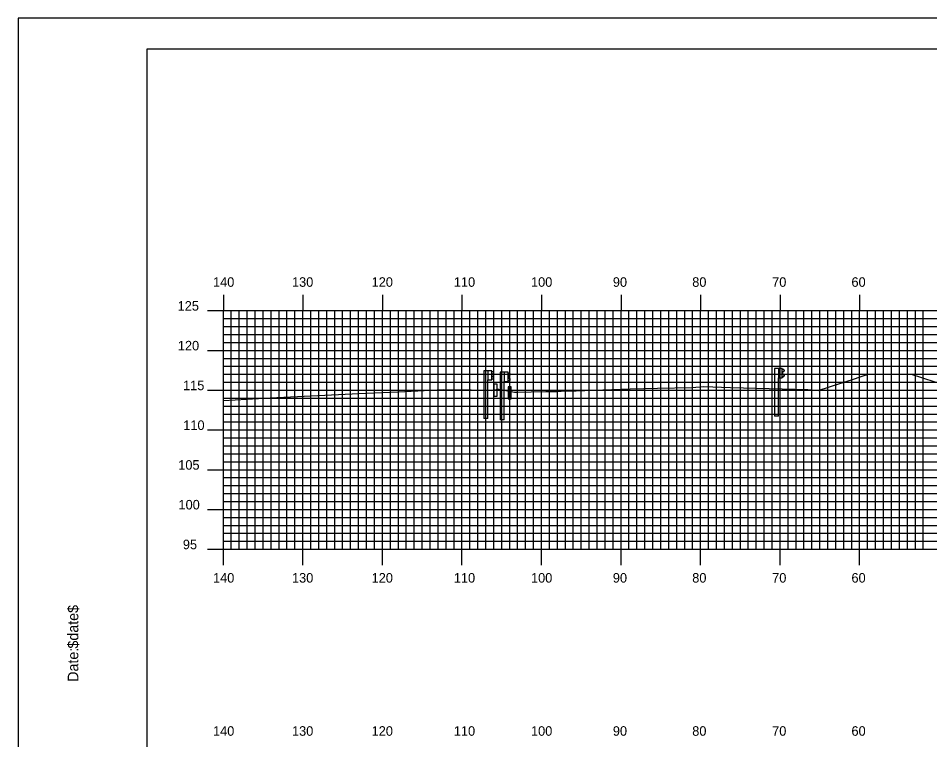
# Model space of a CAD drawing. Extents: x 1754708 to 1755051, y 442591 to 442811.
# Drawn here: x 1754707.7 to 1754822.3, y 442719.8 to 442810.5 of the extents above; entities that cross this region are included whole.
import ezdxf

# ---------------------------------------------------------------- set-up
doc = ezdxf.new("R2010")
doc.units = 0
for name, color, linetype in [('BORDER', 7, 'Continuous'), ('H_V ANNOTATION', 7, 'Continuous'), ('M_Roadway_Centerline', 7, 'Continuous'), ('MAJOR', 7, 'Continuous'), ('MINOR', 7, 'Continuous'), ('PLOT BOUNDARY', 7, 'Continuous'), ('S_Curb_Type_1', 7, 'Continuous'), ('S_Guardrail_Beam', 7, 'Continuous'), ('S_Roadway_Centerline', 7, 'Continuous')]:
    doc.layers.add(name, color=color, linetype=linetype)

msp = doc.modelspace()

# ---------------------------------------------------------------- linework, layer by layer
at = {"layer": 'BORDER'}
msp.add_lwpolyline([(1754723.92, 442596.67), (1755043.92, 442596.67), (1755043.92, 442806.67), (1754723.92, 442806.67)], close=True, dxfattribs=at)
at = {"layer": 'MAJOR'}
for p, q in [((1754733.52, 442775.77), (1754733.52, 442773.77)), ((1754743.52, 442775.77), (1754743.52, 442773.77)), ((1754753.52, 442775.77), (1754753.52, 442773.77)), ((1754763.52, 442775.77), (1754763.52, 442773.77)), ((1754773.52, 442775.77), (1754773.52, 442773.77)), ((1754783.52, 442775.77), (1754783.52, 442773.77)), ((1754793.52, 442775.77), (1754793.52, 442773.77)), ((1754803.52, 442775.77), (1754803.52, 442773.77)), ((1754813.52, 442775.77), (1754813.52, 442773.77)), ((1754731.51, 442773.77), (1754733.52, 442773.77)), ((1754733.52, 442773.77), (1755013.52, 442773.77)), ((1754733.52, 442743.77), (1754733.52, 442773.77)), ((1754733.52, 442743.77), (1754733.52, 442773.77)), ((1754733.52, 442773.77), (1755013.52, 442773.77)), ((1754743.52, 442743.77), (1754743.52, 442773.77)), ((1754753.52, 442743.77), (1754753.52, 442773.77)), ((1754763.52, 442743.77), (1754763.52, 442773.77)), ((1754773.52, 442743.77), (1754773.52, 442773.77)), ((1754783.52, 442743.77), (1754783.52, 442773.77)), ((1754793.52, 442743.77), (1754793.52, 442773.77)), ((1754803.52, 442743.77), (1754803.52, 442773.77)), ((1754813.52, 442743.77), (1754813.52, 442773.77)), ((1754731.51, 442768.77), (1754733.52, 442768.77)), ((1754733.52, 442768.77), (1755013.52, 442768.77)), ((1754731.51, 442763.77), (1754733.52, 442763.77)), ((1754733.52, 442763.77), (1755013.52, 442763.77)), ((1754731.51, 442758.77), (1754733.52, 442758.77)), ((1754733.52, 442758.77), (1755013.52, 442758.77)), ((1754731.51, 442753.77), (1754733.52, 442753.77)), ((1754733.52, 442753.77), (1755013.52, 442753.77)), ((1754731.51, 442748.77), (1754733.52, 442748.77)), ((1754733.52, 442748.77), (1755013.52, 442748.77)), ((1754731.51, 442743.77), (1754733.52, 442743.77)), ((1754733.52, 442743.77), (1755013.52, 442743.77)), ((1754733.52, 442743.77), (1755013.52, 442743.77)), ((1754733.52, 442741.77), (1754733.52, 442743.77)), ((1754743.52, 442741.77), (1754743.52, 442743.77)), ((1754753.52, 442741.77), (1754753.52, 442743.77)), ((1754763.52, 442741.77), (1754763.52, 442743.77)), ((1754773.52, 442741.77), (1754773.52, 442743.77)), ((1754783.52, 442741.77), (1754783.52, 442743.77)), ((1754793.52, 442741.77), (1754793.52, 442743.77)), ((1754803.52, 442741.77), (1754803.52, 442743.77)), ((1754813.52, 442741.77), (1754813.52, 442743.77))]:
    msp.add_line(p, q, dxfattribs=at)
at = {"layer": 'MINOR'}
for p, q in [((1754734.52, 442743.77), (1754734.52, 442773.77)), ((1754735.52, 442743.77), (1754735.52, 442773.77)), ((1754736.52, 442743.77), (1754736.52, 442773.77)), ((1754737.52, 442743.77), (1754737.52, 442773.77)), ((1754738.52, 442743.77), (1754738.52, 442773.77)), ((1754739.52, 442743.77), (1754739.52, 442773.77)), ((1754740.52, 442743.77), (1754740.52, 442773.77)), ((1754741.52, 442743.77), (1754741.52, 442773.77)), ((1754742.52, 442743.77), (1754742.52, 442773.77)), ((1754744.52, 442743.77), (1754744.52, 442773.77)), ((1754745.52, 442743.77), (1754745.52, 442773.77)), ((1754746.52, 442743.77), (1754746.52, 442773.77)), ((1754747.52, 442743.77), (1754747.52, 442773.77)), ((1754748.52, 442743.77), (1754748.52, 442773.77)), ((1754749.52, 442743.77), (1754749.52, 442773.77)), ((1754750.52, 442743.77), (1754750.52, 442773.77)), ((1754751.52, 442743.77), (1754751.52, 442773.77)), ((1754752.52, 442743.77), (1754752.52, 442773.77)), ((1754754.52, 442743.77), (1754754.52, 442773.77)), ((1754755.52, 442743.77), (1754755.52, 442773.77)), ((1754756.52, 442743.77), (1754756.52, 442773.77)), ((1754757.52, 442743.77), (1754757.52, 442773.77)), ((1754758.52, 442743.77), (1754758.52, 442773.77)), ((1754759.52, 442743.77), (1754759.52, 442773.77)), ((1754760.52, 442743.77), (1754760.52, 442773.77)), ((1754761.52, 442743.77), (1754761.52, 442773.77)), ((1754762.52, 442743.77), (1754762.52, 442773.77)), ((1754764.52, 442743.77), (1754764.52, 442773.77)), ((1754765.52, 442743.77), (1754765.52, 442773.77)), ((1754766.52, 442743.77), (1754766.52, 442773.77)), ((1754767.52, 442743.77), (1754767.52, 442773.77)), ((1754768.52, 442743.77), (1754768.52, 442773.77)), ((1754769.52, 442743.77), (1754769.52, 442773.77)), ((1754770.52, 442743.77), (1754770.52, 442773.77)), ((1754771.52, 442743.77), (1754771.52, 442773.77)), ((1754772.52, 442743.77), (1754772.52, 442773.77)), ((1754774.52, 442743.77), (1754774.52, 442773.77)), ((1754775.52, 442743.77), (1754775.52, 442773.77)), ((1754776.52, 442743.77), (1754776.52, 442773.77)), ((1754777.52, 442743.77), (1754777.52, 442773.77)), ((1754778.52, 442743.77), (1754778.52, 442773.77)), ((1754779.52, 442743.77), (1754779.52, 442773.77)), ((1754780.52, 442743.77), (1754780.52, 442773.77)), ((1754781.52, 442743.77), (1754781.52, 442773.77)), ((1754782.52, 442743.77), (1754782.52, 442773.77)), ((1754784.52, 442743.77), (1754784.52, 442773.77)), ((1754785.52, 442743.77), (1754785.52, 442773.77)), ((1754786.52, 442743.77), (1754786.52, 442773.77)), ((1754787.52, 442743.77), (1754787.52, 442773.77)), ((1754788.52, 442743.77), (1754788.52, 442773.77)), ((1754789.52, 442743.77), (1754789.52, 442773.77)), ((1754790.52, 442743.77), (1754790.52, 442773.77)), ((1754791.52, 442743.77), (1754791.52, 442773.77)), ((1754792.52, 442743.77), (1754792.52, 442773.77)), ((1754794.52, 442743.77), (1754794.52, 442773.77)), ((1754795.52, 442743.77), (1754795.52, 442773.77)), ((1754796.52, 442743.77), (1754796.52, 442773.77)), ((1754797.52, 442743.77), (1754797.52, 442773.77)), ((1754798.52, 442743.77), (1754798.52, 442773.77)), ((1754799.52, 442743.77), (1754799.52, 442773.77)), ((1754800.52, 442743.77), (1754800.52, 442773.77)), ((1754801.52, 442743.77), (1754801.52, 442773.77)), ((1754802.52, 442743.77), (1754802.52, 442773.77)), ((1754804.52, 442743.77), (1754804.52, 442773.77)), ((1754805.52, 442743.77), (1754805.52, 442773.77)), ((1754806.52, 442743.77), (1754806.52, 442773.77)), ((1754807.52, 442743.77), (1754807.52, 442773.77)), ((1754808.52, 442743.77), (1754808.52, 442773.77)), ((1754809.52, 442743.77), (1754809.52, 442773.77)), ((1754810.52, 442743.77), (1754810.52, 442773.77)), ((1754811.52, 442743.77), (1754811.52, 442773.77)), ((1754812.52, 442743.77), (1754812.52, 442773.77)), ((1754814.52, 442743.77), (1754814.52, 442773.77)), ((1754815.52, 442743.77), (1754815.52, 442773.77)), ((1754816.52, 442743.77), (1754816.52, 442773.77)), ((1754817.52, 442743.77), (1754817.52, 442773.77)), ((1754818.52, 442743.77), (1754818.52, 442773.77)), ((1754819.52, 442743.77), (1754819.52, 442773.77)), ((1754820.52, 442743.77), (1754820.52, 442773.77)), ((1754821.52, 442743.77), (1754821.52, 442773.77)), ((1754733.52, 442772.77), (1755013.52, 442772.77)), ((1754733.52, 442772.77), (1754735.52, 442772.77)), ((1754733.52, 442771.77), (1755013.52, 442771.77)), ((1754733.52, 442771.77), (1754735.52, 442771.77)), ((1754733.52, 442770.77), (1755013.52, 442770.77)), ((1754733.52, 442770.77), (1754735.52, 442770.77)), ((1754733.52, 442769.77), (1755013.52, 442769.77)), ((1754733.52, 442769.77), (1754735.52, 442769.77)), ((1754733.52, 442767.77), (1755013.52, 442767.77)), ((1754733.52, 442767.77), (1754735.52, 442767.77)), ((1754733.52, 442766.77), (1755013.52, 442766.77)), ((1754733.52, 442766.77), (1754735.52, 442766.77)), ((1754733.52, 442765.77), (1755013.52, 442765.77)), ((1754733.52, 442765.77), (1754735.52, 442765.77)), ((1754733.52, 442764.77), (1755013.52, 442764.77)), ((1754733.52, 442764.77), (1754735.52, 442764.77)), ((1754733.52, 442762.77), (1755013.52, 442762.77)), ((1754733.52, 442762.77), (1754735.52, 442762.77)), ((1754733.52, 442761.77), (1755013.52, 442761.77)), ((1754733.52, 442761.77), (1754735.52, 442761.77)), ((1754733.52, 442760.77), (1755013.52, 442760.77)), ((1754733.52, 442760.77), (1754735.52, 442760.77)), ((1754733.52, 442759.77), (1755013.52, 442759.77)), ((1754733.52, 442759.77), (1754735.52, 442759.77)), ((1754733.52, 442757.77), (1755013.52, 442757.77)), ((1754733.52, 442757.77), (1754735.52, 442757.77)), ((1754733.52, 442756.77), (1755013.52, 442756.77)), ((1754733.52, 442756.77), (1754735.52, 442756.77)), ((1754733.52, 442755.77), (1755013.52, 442755.77)), ((1754733.52, 442755.77), (1754735.52, 442755.77)), ((1754733.52, 442754.77), (1755013.52, 442754.77)), ((1754733.52, 442754.77), (1754735.52, 442754.77)), ((1754733.52, 442752.77), (1755013.52, 442752.77)), ((1754733.52, 442752.77), (1754735.52, 442752.77)), ((1754733.52, 442751.77), (1755013.52, 442751.77)), ((1754733.52, 442751.77), (1754735.52, 442751.77)), ((1754733.52, 442750.77), (1755013.52, 442750.77)), ((1754733.52, 442750.77), (1754735.52, 442750.77)), ((1754733.52, 442749.77), (1755013.52, 442749.77)), ((1754733.52, 442749.77), (1754735.52, 442749.77)), ((1754733.52, 442747.77), (1755013.52, 442747.77)), ((1754733.52, 442747.77), (1754735.52, 442747.77)), ((1754733.52, 442746.77), (1755013.52, 442746.77)), ((1754733.52, 442746.77), (1754735.52, 442746.77)), ((1754733.52, 442745.77), (1755013.52, 442745.77)), ((1754733.52, 442745.77), (1754735.52, 442745.77)), ((1754733.52, 442744.77), (1755013.52, 442744.77)), ((1754733.52, 442744.77), (1754735.52, 442744.77))]:
    msp.add_line(p, q, dxfattribs=at)
at = {"layer": 'PLOT BOUNDARY'}
msp.add_lwpolyline([(1754707.73, 442590.55), (1755047.73, 442590.55), (1755047.73, 442810.55), (1754707.73, 442810.55)], close=True, dxfattribs=at)
at = {"layer": 'S_Curb_Type_1'}
for points in [[(1754767.94, 442764.51), (1754767.52, 442764.51), (1754767.52, 442763.01), (1754767.94, 442763.01)], [(1754769.72, 442764.19), (1754769.31, 442764.19), (1754769.31, 442762.69), (1754769.72, 442762.69)]]:
    msp.add_lwpolyline(points, close=True, dxfattribs=at)
at = {"layer": 'S_Guardrail_Beam'}
for p, q in [((1754766.28, 442766.22), (1754766.28, 442760.22)), ((1754766.77, 442766.22), (1754766.28, 442766.22)), ((1754767.26, 442766.22), (1754766.77, 442766.22)), ((1754766.77, 442766.22), (1754766.77, 442765.06)), ((1754767.26, 442765.06), (1754767.26, 442766.22)), ((1754767.26, 442766.15), (1754767.34, 442766.13)), ((1754767.28, 442765.68), (1754767.28, 442765.59)), ((1754767.51, 442765.88), (1754767.31, 442765.75)), ((1754767.31, 442765.53), (1754767.51, 442765.39)), ((1754767.36, 442766.13), (1754767.51, 442766.03)), ((1754768.33, 442766.02), (1754768.33, 442760.02)), ((1754768.83, 442766.02), (1754768.33, 442766.02)), ((1754769.32, 442766.02), (1754768.83, 442766.02)), ((1754768.83, 442766.02), (1754768.83, 442764.85)), ((1754769.32, 442764.85), (1754769.32, 442766.02)), ((1754769.32, 442765.94), (1754769.4, 442765.93)), ((1754769.33, 442765.48), (1754769.33, 442765.39)), ((1754769.56, 442765.68), (1754769.36, 442765.54)), ((1754769.41, 442765.92), (1754769.56, 442765.82)), ((1754802.81, 442766.5), (1754802.81, 442760.5)), ((1754803.3, 442766.5), (1754802.81, 442766.5)), ((1754803.79, 442766.5), (1754803.3, 442766.5)), ((1754803.3, 442766.5), (1754803.3, 442765.33)), ((1754803.79, 442765.33), (1754803.79, 442766.5)), ((1754803.79, 442766.43), (1754803.87, 442766.41)), ((1754803.87, 442765.42), (1754803.79, 442765.41)), ((1754803.8, 442765.96), (1754803.8, 442765.87)), ((1754804.03, 442766.16), (1754803.84, 442766.03)), ((1754803.84, 442765.81), (1754804.03, 442765.67)), ((1754803.89, 442766.41), (1754804.03, 442766.31)), ((1754804.03, 442765.53), (1754803.89, 442765.43)), ((1754766.77, 442760.22), (1754766.77, 442765.06)), ((1754766.77, 442765.06), (1754767.26, 442765.06)), ((1754767.34, 442765.14), (1754767.26, 442765.13)), ((1754767.51, 442765.25), (1754767.36, 442765.15)), ((1754768.83, 442760.02), (1754768.83, 442764.85)), ((1754768.83, 442764.85), (1754769.32, 442764.85)), ((1754769.4, 442764.94), (1754769.32, 442764.92)), ((1754769.36, 442765.32), (1754769.56, 442765.19)), ((1754769.56, 442765.04), (1754769.41, 442764.94)), ((1754803.3, 442760.5), (1754803.3, 442765.33)), ((1754803.3, 442765.33), (1754803.79, 442765.33)), ((1754766.77, 442760.22), (1754766.28, 442760.22)), ((1754768.83, 442760.02), (1754768.33, 442760.02)), ((1754803.3, 442760.5), (1754802.81, 442760.5))]:
    msp.add_line(p, q, dxfattribs=at)
for centre, major_axis, start_param, end_param in [((1754767.35, 442765.68), (-0.0789, 0), 5.323254, 6.283185), ((1754767.35, 442765.59), (-0.0789, 0), 6.283185, 7.243116), ((1754767.34, 442766.09), (0.0417, 0), 0.959931, 1.396263), ((1754767.45, 442765.96), (0.0877, 0), 5.323254, 7.243116), ((1754767.45, 442765.32), (0.0877, 0), 5.323254, 7.243116), ((1754769.41, 442765.48), (-0.0789, 0), 5.323254, 6.283185), ((1754769.41, 442765.39), (-0.0789, 0), 6.283185, 7.243116), ((1754769.39, 442765.89), (0.0417, 0), 0.959931, 1.396263), ((1754769.51, 442765.75), (0.0877, 0), 5.323254, 7.243116), ((1754803.88, 442765.96), (-0.0789, 0), 5.323254, 6.283185), ((1754803.88, 442765.87), (-0.0789, 0), 6.283185, 7.243116), ((1754803.86, 442766.37), (0.0417, 0), 0.959931, 1.396263), ((1754803.86, 442765.46), (0.0417, 0), 4.886922, 5.323254), ((1754803.98, 442766.23), (0.0877, 0), 5.323254, 7.243116), ((1754803.98, 442765.6), (0.0877, 0), 5.323254, 7.243116), ((1754767.34, 442765.18), (0.0417, 0), 4.886922, 5.323254), ((1754769.39, 442764.98), (0.0417, 0), 4.886922, 5.323254), ((1754769.51, 442765.12), (0.0877, 0), 5.323254, 7.243116)]:
    msp.add_ellipse(centre, major_axis=major_axis, ratio=0.995501, start_param=start_param, end_param=end_param, dxfattribs=at)
at = {"layer": 'S_Roadway_Centerline'}
for points in [[(1754808.32, 442763.74), (1754808.32, 442763.74), (1754811.16, 442764.65), (1754811.3, 442764.7), (1754811.52, 442764.77), (1754811.52, 442764.77), (1754811.52, 442764.77), (1754811.52, 442764.77), (1754812.5, 442765.09), (1754813.85, 442765.52), (1754814.62, 442765.77), (1754814.64, 442765.77), (1754814.73, 442765.77), (1754817.57, 442765.77), (1754819.89, 442765.77), (1754819.96, 442765.77), (1754820, 442765.77), (1754821.29, 442765.35), (1754823.1, 442764.77)], [(1754733.52, 442762.46), (1754739.42, 442762.8), (1754750.56, 442763.35), (1754755.5, 442763.57), (1754761.26, 442763.87), (1754764.66, 442763.8), (1754767.19, 442763.73), (1754767.46, 442763.76), (1754767.86, 442763.86), (1754767.94, 442763.93), (1754768.16, 442763.9), (1754769.72, 442763.6), (1754770.13, 442763.53), (1754770.36, 442763.5), (1754774.06, 442763.6), (1754775.45, 442763.62), (1754775.99, 442763.64), (1754777.89, 442763.7), (1754780.06, 442763.77), (1754783.55, 442763.88), (1754784.66, 442763.93), (1754788.12, 442764.03), (1754792.41, 442764.1), (1754793.93, 442764.22), (1754797.28, 442764.11), (1754807.01, 442763.86), (1754807.37, 442763.82), (1754808.14, 442763.77)]]:
    msp.add_lwpolyline(points, dxfattribs=at)

# ---------------------------------------------------------------- texts
at = {"layer": 'BORDER'}
for s, p in [('$date$', (1754715.29, 442731.28)), ('$date$', (1754715.29, 442731.28)), ('Date:', (1754715.29, 442727.1)), ('Date:', (1754715.29, 442727.1))]:
    msp.add_text(s, height=1.339, rotation=90, dxfattribs=at).set_placement(p)
at = {"layer": 'H_V ANNOTATION'}
for s, p in [('140', (1754732.22, 442776.77)), ('130', (1754742.15, 442776.77)), ('120', (1754752.16, 442776.77)), ('110', (1754762.5, 442776.77)), ('100', (1754772.2, 442776.77)), ('90', (1754782.49, 442776.77)), ('80', (1754792.47, 442776.77)), ('70', (1754802.52, 442776.77)), ('60', (1754812.49, 442776.77)), ('125', (1754727.77, 442773.77)), ('120', (1754727.8, 442768.77)), ('115', (1754728.45, 442763.77)), ('110', (1754728.48, 442758.77)), ('105', (1754727.85, 442753.77)), ('100', (1754727.88, 442748.77)), ('95', (1754728.43, 442743.77)), ('140', (1754732.22, 442739.57)), ('130', (1754742.15, 442739.57)), ('120', (1754752.16, 442739.57)), ('110', (1754762.5, 442739.57)), ('100', (1754772.2, 442739.57)), ('90', (1754782.49, 442739.57)), ('80', (1754792.47, 442739.57)), ('70', (1754802.52, 442739.57)), ('60', (1754812.49, 442739.57)), ('140', (1754732.22, 442720.31)), ('130', (1754742.15, 442720.31)), ('120', (1754752.16, 442720.31)), ('110', (1754762.5, 442720.31)), ('100', (1754772.2, 442720.31)), ('90', (1754782.49, 442720.31)), ('80', (1754792.47, 442720.31)), ('70', (1754802.52, 442720.31)), ('60', (1754812.49, 442720.31))]:
    msp.add_text(s, height=1.2, dxfattribs=at).set_placement(p)
at = {"layer": 'M_Roadway_Centerline'}
for s, p in [('C', (1754784.66, 442763.93)), ('L', (1754784.66, 442763.92))]:
    msp.add_text(s, height=0.0146, dxfattribs=at).set_placement(p)
at = {"layer": 'MAJOR'}
msp.add_text('-', height=0.012, dxfattribs=at).set_placement((1754733.51, 442743.77))

doc.saveas('drawing.dxf')
